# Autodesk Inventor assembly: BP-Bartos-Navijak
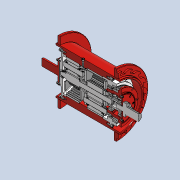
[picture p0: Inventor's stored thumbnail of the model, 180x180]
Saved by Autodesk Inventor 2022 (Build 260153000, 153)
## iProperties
Created: 2025-05
Part Number: BP-Bartos-Navijak
Document SubType Name: Assembly
Designer: jbart
Mass: 166693 g
Surface Area: 105788 cm^2
Volume: 131194 cm^3
Density: 1.27058 g/cm^3
Author: jbart
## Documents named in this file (39)
- C:\Users\jbart\OneDrive\Dokumenty\Inventor\Převodovka navijáku\BP-Bartos-Navijak.iam
- C:\Users\jbart\OneDrive\Dokumenty\Inventor\Převodovka navijáku\Bočnice.ipt
- C:\Users\jbart\OneDrive\Dokumenty\Inventor\Content Center Files\R2022\cs-CZ\CSN 02 4630\CSN 02 4630 - 6414.ipt
- C:\Users\jbart\OneDrive\Dokumenty\Inventor\Content Center Files\R2022\cs-CZ\CSN 02 2931\CSN 02 2931 - 180.ipt
- C:\Users\jbart\OneDrive\Dokumenty\Inventor\Převodovka navijáku\Víčko.ipt
- C:\Users\jbart\OneDrive\Dokumenty\Inventor\Převodovka navijáku\Pouzdro.ipt
- C:\Users\jbart\OneDrive\Dokumenty\Inventor\Content Center Files\R2022\cs-CZ\CSN 02 2930\CSN 02 2930 - 70.ipt
- C:\Users\jbart\OneDrive\Dokumenty\Inventor\Převodovka navijáku\Hřídel I.ipt
- C:\Users\jbart\OneDrive\Dokumenty\Inventor\Content Center Files\R2022\cs-CZ\CSN 02 2562  A\CSN 02 2562 - 16x10x50.ipt
- C:\Users\jbart\OneDrive\Dokumenty\Inventor\Content Center Files\R2022\cs-CZ\CSN 02 4720\CSN  02 4720 - 32952.ipt
- C:\Users\jbart\OneDrive\Dokumenty\Inventor\Content Center Files\R2022\cs-CZ\CSN 02 4720\CSN  02 4720 - 32948.ipt
- C:\Users\jbart\OneDrive\Dokumenty\Inventor\Převodovka navijáku\Pouzdro II.ipt
- C:\Users\jbart\OneDrive\Dokumenty\Inventor\Převodovka navijáku\Hřídel II.iam
- C:\Users\jbart\OneDrive\Dokumenty\Inventor\Content Center Files\R2022\cs-CZ\CSN 02 4630\CSN 02 4630 - 6208.ipt
- C:\Users\jbart\OneDrive\Dokumenty\Inventor\Content Center Files\R2022\cs-CZ\CSN 02 2930\CSN 02 2930 - 40.ipt
- C:\Users\jbart\OneDrive\Dokumenty\Inventor\Převodovka navijáku\Unášeč A-1.ipt
- C:\Users\jbart\OneDrive\Dokumenty\Inventor\Převodovka navijáku\Hřídel IV.ipt
- C:\Users\jbart\OneDrive\Dokumenty\Inventor\Převodovka navijáku\Distanční kroužek.ipt
- C:\Users\jbart\OneDrive\Dokumenty\Inventor\Content Center Files\R2022\cs-CZ\CSN 02 2930\CSN 02 2930 - 50.ipt
- C:\Users\jbart\OneDrive\Dokumenty\Inventor\Převodovka navijáku\Satelit A.iam
- C:\Users\jbart\OneDrive\Dokumenty\Inventor\Content Center Files\R2022\cs-CZ\CSN 02 4630\CSN 02 4630 - 6010.ipt
- C:\Users\jbart\OneDrive\Dokumenty\Inventor\Převodovka navijáku\Unášeč A-2.ipt
- C:\Users\jbart\OneDrive\Dokumenty\Inventor\Převodovka navijáku\Hřídel III.iam
- C:\Users\jbart\OneDrive\Dokumenty\Inventor\Převodovka navijáku\Distanční kroužek II.ipt
- C:\Users\jbart\OneDrive\Dokumenty\Inventor\Převodovka navijáku\Unášeč B-2.ipt
- C:\Users\jbart\OneDrive\Dokumenty\Inventor\Content Center Files\R2022\cs-CZ\CSN 02 1143  A\CSN 02 1143 - M12 x 1,75 x 20(1).ipt
- C:\Users\jbart\OneDrive\Dokumenty\Inventor\Content Center Files\R2022\cs-CZ\CSN 02 1143  A\CSN 02 1143 - M12 x 1,75 x 25(1).ipt
- C:\Users\jbart\OneDrive\Dokumenty\Inventor\Převodovka navijáku\Satelit B.iam
- C:\Users\jbart\OneDrive\Dokumenty\Inventor\Převodovka navijáku\Hřídel V.ipt
- C:\Users\jbart\OneDrive\Dokumenty\Inventor\Převodovka navijáku\Unášeč B-1.ipt
- C:\Users\jbart\OneDrive\Dokumenty\Inventor\Převodovka navijáku\Korunové kolo 2.iam
- C:\Users\jbart\OneDrive\Dokumenty\Inventor\Převodovka navijáku\Korunové kolo 1.iam
- C:\Users\jbart\OneDrive\Dokumenty\Inventor\Content Center Files\R2022\cs-CZ\CSN 02 1143  A\CSN 02 1143 - M16 x 2 x 45(1).ipt
- C:\Users\jbart\OneDrive\Dokumenty\Inventor\Převodovka navijáku\Víčko II.ipt
- C:\Users\jbart\OneDrive\Dokumenty\Inventor\Převodovka navijáku\Výstup.ipt
- C:\Users\jbart\OneDrive\Dokumenty\Inventor\Content Center Files\R2022\cs-CZ\CSN 02 1143  A\CSN 02 1143 - M12 x 1,75 x 22(1).ipt
- C:\Users\jbart\OneDrive\Dokumenty\Inventor\Převodovka navijáku\Buben - nový.iam
- C:\Users\jbart\OneDrive\Dokumenty\Inventor\Content Center Files\R2022\cs-CZ\CSN 02 9281\CSN 02 9281 - 16x2.ipt
- C:\Users\jbart\OneDrive\Dokumenty\Inventor\Content Center Files\R2022\cs-CZ\CSN 02 1143  A\CSN 02 1143 - M16 x 2 x 60(1).ipt
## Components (114 placed, 38 different names)
1. Bočnice:1 — Proti sobě:1, Stejný směr:1, Stejný směr:2, Proti sobě:2, Proti sobě:3, Proti sobě:4, Proti sobě:5, Proti sobě:6, Proti sobě:9, Proti sobě:10, Proti sobě:15, Proti sobě:16, Proti sobě:23, Proti sobě:24, Proti sobě:25, Proti sobě:26, Proti sobě:27, Proti sobě:37, Proti sobě:97, Proti sobě:98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
2. CSN 02 4630 6414:1 — Proti sobě:2, Proti sobě:3, Proti sobě:13, Proti sobě:14
3. CSN 02 2931 180:1 — Proti sobě:4, Proti sobě:5, Proti sobě:6
4. CSN 02 4630 6414:2
5. Víčko:1 — Proti sobě:9, Proti sobě:10, Proti sobě:16, Proti sobě:22, Proti sobě:99, Proti sobě:100
6. Pouzdro:1 — Proti sobě:11, Proti sobě:12, Proti sobě:13, Proti sobě:14, Proti sobě:20, Proti sobě:21, Proti sobě:30, Proti sobě:31, Proti sobě:32
7. CSN 02 2930 70:1 — Proti sobě:11, Proti sobě:12, Proti sobě:15
8. Hřídel I:1 — Proti sobě:20, Proti sobě:22, Proti sobě:176, Stejný směr:66
9. CSN 02 2562 A 16x10x50:1 — Proti sobě:21
10. CSN 02 4720 32952:1 — Proti sobě:23, Proti sobě:24, Proti sobě:28
11. CSN 02 4720 32948:1 — Proti sobě:25, Proti sobě:26
12. Pouzdro II:1 — Proti sobě:27, Proti sobě:28, Proti sobě:155, Proti sobě:157, Proti sobě:174, Proti sobě:175, Proti sobě:181
13. Hřídel II:1 [sub-assembly] — Proti sobě:30, Proti sobě:31, Proti sobě:32, Proti sobě:33, Proti sobě:34, Proti sobě:35, Proti sobě:36, Proti sobě:38, Stejný směr:59, Proti sobě:88, Proti sobě:91, Proti sobě:94, Proti sobě:96, Rotace:1, Rotace:2, Rotace:3, Rotace:4
14. CSN 02 4630 6208:1 — Proti sobě:33, Proti sobě:34
15. CSN 02 2930 40:1 — Proti sobě:35, Proti sobě:36, Proti sobě:37
16. Unášeč A-1:1 — Proti sobě:38, Proti sobě:53, Proti sobě:54, Proti sobě:55, Proti sobě:69, Proti sobě:70, Proti sobě:71, Proti sobě:85, Proti sobě:86, Proti sobě:87
17. Unášeč A-2:1 — Proti sobě:88, Proti sobě:90, Proti sobě:92, Proti sobě:93, Stejný směr:60, Rotace:4
18. Hřídel III:1 [sub-assembly] — Proti sobě:91, Proti sobě:93, Stejný směr:60, Proti sobě:95, Rotace:5, Rotace:6, Rotace:7, Rotace:8
19. Distanční kroužek II:1 — Proti sobě:94, Proti sobě:95
20. Unášeč B-2:1 — Proti sobě:96, Proti sobě:97, Proti sobě:98, Proti sobě:101, Proti sobě:102, Proti sobě:116, Proti sobě:117, Proti sobě:119, Proti sobě:133, Proti sobě:134, Proti sobě:135, Proti sobě:149, Proti sobě:150, Proti sobě:151, Proti sobě:152
21. Unášeč B-1:1 — Proti sobě:152, Proti sobě:153, Proti sobě:154
22. Korunové kolo 2:1 [sub-assembly] — Proti sobě:155, Stejný směr:62, Stejný směr:64, Rotace:8, Proti sobě:177
23. Korunové kolo 1:1 [sub-assembly] — Proti sobě:157, Stejný směr:63, Proti sobě:178
24. Víčko II:1 — Proti sobě:166, Proti sobě:167, Proti sobě:168, Proti sobě:169, Proti sobě:170
25. Výstup:1 — Proti sobě:168, Proti sobě:169, Proti sobě:170, Proti sobě:171, Proti sobě:172
26. Buben - nový:1 [sub-assembly] — Proti sobě:176, Proti sobě:177, Proti sobě:178, Proti sobě:179, Proti sobě:180, Proti sobě:181, Proti sobě:182, Proti sobě:183, Proti sobě:184, Proti sobě:185
27. CSN 02 1143 A M16 x 60:1 — Proti sobě:184, Proti sobě:185
28. CSN 02 9281 16x2:1 — Proti sobě:182, Proti sobě:183
29. Hřídel IV:1 — Proti sobě:53, Proti sobě:92
30. Distanční kroužek:1 — Proti sobě:55
31. Distanční kroužek:2 — Proti sobě:90
32. CSN 02 2930 50:1
33. CSN 02 2930 50:2 — Proti sobě:54
34. Satelit A:1 [sub-assembly] — Stejný směr:59, Stejný směr:63, Rotace:1
35. CSN 02 4630 6010:1
36. CSN 02 4630 6010:2
37. Hřídel IV:2 — Proti sobě:69
38. Distanční kroužek:3
39. Distanční kroužek:4
40. CSN 02 2930 50:3
41. CSN 02 2930 50:4 — Proti sobě:70
42. Satelit A:2 [sub-assembly] — Rotace:2
43. CSN 02 4630 6010:3 — Proti sobě:71
44. CSN 02 4630 6010:4
45. Hřídel IV:3 — Proti sobě:85
46. Distanční kroužek:5 — Proti sobě:87
47. Distanční kroužek:6
48. CSN 02 2930 50:5
49. CSN 02 2930 50:6 — Proti sobě:86
50. Satelit A:3 [sub-assembly] — Rotace:3
51. CSN 02 4630 6010:5
52. CSN 02 4630 6010:6
53. Satelit B:1 [sub-assembly] — Rotace:5
54. Hřídel V:1 — Proti sobě:116, Proti sobě:153
55. CSN 02 4630 6010:7
56. CSN 02 4630 6010:8
57. Distanční kroužek:7
58. Distanční kroužek:8 — Proti sobě:119
59. CSN 02 2930 50:7
60. CSN 02 2930 50:8 — Proti sobě:117, Proti sobě:118
61. Satelit B:2 [sub-assembly] — Stejný směr:62, Rotace:7
62. Hřídel V:2 — Proti sobě:133
63. CSN 02 4630 6010:9
64. CSN 02 4630 6010:10
65. Distanční kroužek:9 — Proti sobě:154
66. Distanční kroužek:10 — Proti sobě:135
67. CSN 02 2930 50:9
68. CSN 02 2930 50:10 — Proti sobě:134
69. Satelit B:3 [sub-assembly] — Rotace:6
70. Hřídel V:3 — Proti sobě:149
71. CSN 02 4630 6010:11
72. CSN 02 4630 6010:12
73. Distanční kroužek:11
74. Distanční kroužek:12 — Proti sobě:151
75. CSN 02 2930 50:11
76. CSN 02 2930 50:12 — Proti sobě:150
77. CSN 02 1143 A M12 x 20:1 — Proti sobě:99, Proti sobě:100
78. CSN 02 1143 A M12 x 20:2
79. CSN 02 1143 A M12 x 20:3
80. CSN 02 1143 A M12 x 20:4
81. CSN 02 1143 A M12 x 20:5
82. CSN 02 1143 A M12 x 20:6
83. CSN 02 1143 A M12 x 20:7
84. CSN 02 1143 A M12 x 20:8
85. CSN 02 1143 A M12 x 25:1 — Proti sobě:101, Proti sobě:102
86. CSN 02 1143 A M12 x 25:2
87. CSN 02 1143 A M12 x 25:3
88. CSN 02 1143 A M12 x 25:4
89. CSN 02 1143 A M12 x 25:5
90. CSN 02 1143 A M12 x 25:6
91. CSN 02 1143 A M16 x 45:9 — Proti sobě:166, Proti sobě:167
92. CSN 02 1143 A M16 x 45:10 — Proti sobě:180
93. CSN 02 1143 A M16 x 45:11
94. CSN 02 1143 A M16 x 45:12
95. CSN 02 1143 A M16 x 45:13
96. CSN 02 1143 A M16 x 45:14
97. CSN 02 1143 A M16 x 45:15
98. CSN 02 1143 A M16 x 45:16
99. CSN 02 1143 A M12 x 22:1 — Proti sobě:171, Proti sobě:172
100. CSN 02 1143 A M12 x 22:2
101. CSN 02 1143 A M12 x 22:3
102. CSN 02 1143 A M12 x 22:4
103. CSN 02 1143 A M12 x 22:5
104. CSN 02 1143 A M12 x 22:6
105. CSN 02 1143 A M12 x 22:7
106. CSN 02 1143 A M12 x 22:8
107. CSN 02 1143 A M16 x 45:1 — Proti sobě:174, Proti sobě:175, Proti sobě:179
108. CSN 02 1143 A M16 x 45:17
109. CSN 02 1143 A M16 x 45:18
110. CSN 02 1143 A M16 x 45:19
111. CSN 02 1143 A M16 x 45:20
112. CSN 02 1143 A M16 x 45:21
113. CSN 02 1143 A M16 x 45:22
114. CSN 02 1143 A M16 x 45:23
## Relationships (106: Mate 89, Flush 9, RelateRotation 8)
- Proti sobě:1 [Mate]: Bočnice:1
- Stejný směr:1 [Flush]: Bočnice:1
- Stejný směr:2 [Flush]: Bočnice:1
- Proti sobě:2 [Mate]: Bočnice:1 ↔ CSN 02 4630 6414:1
- Proti sobě:3 [Mate]: Bočnice:1 ↔ CSN 02 4630 6414:1
- Proti sobě:4 [Mate]: Bočnice:1 ↔ CSN 02 2931 180:1
- Proti sobě:5 [Mate]: Bočnice:1 ↔ CSN 02 2931 180:1
- Proti sobě:6 [Mate]: Bočnice:1 ↔ CSN 02 2931 180:1
- Proti sobě:9 [Mate]: Bočnice:1 ↔ Víčko:1
- Proti sobě:10 [Mate]: Bočnice:1 ↔ Víčko:1
- Proti sobě:11 [Mate]: Pouzdro:1 ↔ CSN 02 2930 70:1
- Proti sobě:12 [Mate]: Pouzdro:1 ↔ CSN 02 2930 70:1
- Proti sobě:13 [Mate]: CSN 02 4630 6414:1 ↔ Pouzdro:1
- Proti sobě:14 [Mate]: CSN 02 4630 6414:1 ↔ Pouzdro:1
- Proti sobě:15 [Mate]: Bočnice:1 ↔ CSN 02 2930 70:1
- Proti sobě:16 [Mate]: Bočnice:1 ↔ Víčko:1
- Proti sobě:20 [Mate]: Pouzdro:1 ↔ Hřídel I:1
- Proti sobě:21 [Mate]: Pouzdro:1 ↔ CSN 02 2562 A 16x10x50:1
- Proti sobě:22 [Mate]: Víčko:1 ↔ Hřídel I:1
- Proti sobě:23 [Mate]: Bočnice:1 ↔ CSN 02 4720 32952:1
- Proti sobě:24 [Mate]: Bočnice:1 ↔ CSN 02 4720 32952:1
- Proti sobě:25 [Mate]: Bočnice:1 ↔ CSN 02 4720 32948:1
- Proti sobě:26 [Mate]: Bočnice:1 ↔ CSN 02 4720 32948:1
- Proti sobě:27 [Mate]: Bočnice:1 ↔ Pouzdro II:1
- Proti sobě:28 [Mate]: CSN 02 4720 32952:1 ↔ Pouzdro II:1
- Proti sobě:30 [Mate]: Pouzdro:1 ↔ Hřídel II:1
- Proti sobě:31 [Mate]: Pouzdro:1 ↔ Hřídel II:1
- Proti sobě:32 [Mate]: Pouzdro:1 ↔ Hřídel II:1
- Proti sobě:33 [Mate]: Hřídel II:1 ↔ CSN 02 4630 6208:1
- Proti sobě:34 [Mate]: Hřídel II:1 ↔ CSN 02 4630 6208:1
- Proti sobě:35 [Mate]: Hřídel II:1 ↔ CSN 02 2930 40:1
- Proti sobě:36 [Mate]: Hřídel II:1 ↔ CSN 02 2930 40:1
- Proti sobě:37 [Mate]: Bočnice:1 ↔ CSN 02 2930 40:1
- Proti sobě:38 [Mate]: Hřídel II:1 ↔ Unášeč A-1:1
- Proti sobě:53 [Mate]: Unášeč A-1:1 ↔ Hřídel IV:1
- Proti sobě:54 [Mate]: Unášeč A-1:1 ↔ CSN 02 2930 50:2
- Proti sobě:55 [Mate]: Unášeč A-1:1 ↔ Distanční kroužek:1
- Proti sobě:69 [Mate]: Unášeč A-1:1 ↔ Hřídel IV:2
- Proti sobě:70 [Mate]: Unášeč A-1:1 ↔ CSN 02 2930 50:4
- Proti sobě:71 [Mate]: Unášeč A-1:1 ↔ CSN 02 4630 6010:3
- Proti sobě:85 [Mate]: Unášeč A-1:1 ↔ Hřídel IV:3
- Proti sobě:86 [Mate]: Unášeč A-1:1 ↔ CSN 02 2930 50:6
- Proti sobě:87 [Mate]: Unášeč A-1:1 ↔ Distanční kroužek:5
- Stejný směr:59 [Flush]: Hřídel II:1 ↔ Satelit A:1
- Proti sobě:88 [Mate]: Hřídel II:1 ↔ Unášeč A-2:1
- Proti sobě:90 [Mate]: Unášeč A-2:1 ↔ Distanční kroužek:2
- Proti sobě:91 [Mate]: Hřídel II:1 ↔ Hřídel III:1
- Proti sobě:92 [Mate]: Unášeč A-2:1 ↔ Hřídel IV:1
- Proti sobě:93 [Mate]: Unášeč A-2:1 ↔ Hřídel III:1
- Stejný směr:60 [Flush]: Unášeč A-2:1 ↔ Hřídel III:1
- Proti sobě:94 [Mate]: Hřídel II:1 ↔ Distanční kroužek II:1
- Proti sobě:95 [Mate]: Hřídel III:1 ↔ Distanční kroužek II:1
- Proti sobě:96 [Mate]: Hřídel II:1 ↔ Unášeč B-2:1
- Proti sobě:97 [Mate]: Bočnice:1 ↔ Unášeč B-2:1
- Proti sobě:98 [Mate]: Bočnice:1 ↔ Unášeč B-2:1
- Proti sobě:99 [Mate]: Víčko:1 ↔ CSN 02 1143 A M12 x 20:1
- Proti sobě:100 [Mate]: Víčko:1 ↔ CSN 02 1143 A M12 x 20:1
- Proti sobě:101 [Mate]: Unášeč B-2:1 ↔ CSN 02 1143 A M12 x 25:1
- Proti sobě:102 [Mate]: Unášeč B-2:1 ↔ CSN 02 1143 A M12 x 25:1
- Proti sobě:116 [Mate]: Unášeč B-2:1 ↔ Hřídel V:1
- Proti sobě:117 [Mate]: Unášeč B-2:1 ↔ CSN 02 2930 50:8
- Proti sobě:118 [Mate]: Bočnice:1 ↔ CSN 02 2930 50:8
- Proti sobě:119 [Mate]: Unášeč B-2:1 ↔ Distanční kroužek:8
- Proti sobě:133 [Mate]: Unášeč B-2:1 ↔ Hřídel V:2
- Proti sobě:134 [Mate]: Unášeč B-2:1 ↔ CSN 02 2930 50:10
- Proti sobě:135 [Mate]: Unášeč B-2:1 ↔ Distanční kroužek:10
- Proti sobě:149 [Mate]: Unášeč B-2:1 ↔ Hřídel V:3
- Proti sobě:150 [Mate]: Unášeč B-2:1 ↔ CSN 02 2930 50:12
- Proti sobě:151 [Mate]: Unášeč B-2:1 ↔ Distanční kroužek:12
- Proti sobě:152 [Mate]: Unášeč B-2:1 ↔ Unášeč B-1:1
- Proti sobě:153 [Mate]: Unášeč B-1:1 ↔ Hřídel V:1
- Proti sobě:154 [Mate]: Unášeč B-1:1 ↔ Distanční kroužek:9
- Proti sobě:155 [Mate]: Pouzdro II:1 ↔ Korunové kolo 2:1
- Stejný směr:62 [Flush]: Korunové kolo 2:1 ↔ Satelit B:2
- Proti sobě:157 [Mate]: Pouzdro II:1 ↔ Korunové kolo 1:1
- Stejný směr:63 [Flush]: Korunové kolo 1:1 ↔ Satelit A:1
- Stejný směr:64 [Flush]: Korunové kolo 2:1
- Proti sobě:166 [Mate]: Víčko II:1 ↔ CSN 02 1143 A M16 x 45:9
- Proti sobě:167 [Mate]: Víčko II:1 ↔ CSN 02 1143 A M16 x 45:9
- Proti sobě:168 [Mate]: Víčko II:1 ↔ Výstup:1
- Proti sobě:169 [Mate]: Víčko II:1 ↔ Výstup:1
- Proti sobě:170 [Mate]: Víčko II:1 ↔ Výstup:1
- Proti sobě:171 [Mate]: Výstup:1 ↔ CSN 02 1143 A M12 x 22:1
- Proti sobě:172 [Mate]: Výstup:1 ↔ CSN 02 1143 A M12 x 22:1
- Stejný směr:65 [Flush]: Bočnice:1
- Rotace:1 [RelateRotation]: Hřídel II:1 ↔ Satelit A:1
- Rotace:2 [RelateRotation]: Hřídel II:1 ↔ Satelit A:2
- Rotace:3 [RelateRotation]: Hřídel II:1 ↔ Satelit A:3
- Rotace:4 [RelateRotation]: Hřídel II:1 ↔ Unášeč A-2:1
- Rotace:5 [RelateRotation]: Hřídel III:1 ↔ Satelit B:1
- Rotace:6 [RelateRotation]: Hřídel III:1 ↔ Satelit B:3
- Rotace:7 [RelateRotation]: Hřídel III:1 ↔ Satelit B:2
- Rotace:8 [RelateRotation]: Hřídel III:1 ↔ Korunové kolo 2:1
- Proti sobě:174 [Mate]: Pouzdro II:1 ↔ CSN 02 1143 A M16 x 45:1
- Proti sobě:175 [Mate]: Pouzdro II:1 ↔ CSN 02 1143 A M16 x 45:1
- Proti sobě:176 [Mate]: Hřídel I:1 ↔ Buben - nový:1
- Proti sobě:177 [Mate]: Korunové kolo 2:1 ↔ Buben - nový:1
- Proti sobě:178 [Mate]: Korunové kolo 1:1 ↔ Buben - nový:1
- Proti sobě:179 [Mate]: Buben - nový:1 ↔ CSN 02 1143 A M16 x 45:1
- Proti sobě:180 [Mate]: Buben - nový:1 ↔ CSN 02 1143 A M16 x 45:10
- Proti sobě:181 [Mate]: Pouzdro II:1 ↔ Buben - nový:1
- Proti sobě:182 [Mate]: Buben - nový:1 ↔ CSN 02 9281 16x2:1
- Proti sobě:183 [Mate]: Buben - nový:1 ↔ CSN 02 9281 16x2:1
- Proti sobě:184 [Mate]: Buben - nový:1 ↔ CSN 02 1143 A M16 x 60:1
- Proti sobě:185 [Mate]: Buben - nový:1 ↔ CSN 02 1143 A M16 x 60:1
- Stejný směr:66 [Flush]: Hřídel I:1
## Named parameters: d19_d13 = 0, d20_d14 = 0, d21_d15 = 0, d61_d108 = 0, d62_d109 = 0, d63_d110 = 0, d64_d111 = 0, d65_d112 = 0, d66_d113 = 0, d67_d114 = 0, d68_d115 = 0, d69_d116 = 0, d70_d117 = 0, d71_d118 = 0, d72_d119 = 0, d73_d107 = 0, d77_d108 = 0, d78_d109 = 0, d79_d110 = 0, d80_d111 = 0, d81_d112 = 0, d82_d113 = 0, d83_d114 = 0, d84_d115 = 0, d85_d116 = 0, d86_d117 = 0, d87_d118 = 0, d88_d119 = 0, d89_d107 = 0, d66_d56 = 0, d67_d57 = 0, d68_d58 = 0, d69_d46 = 0, d70_d47 = 0, d71_d48 = 0, d72_d49 = 0, d73_d50 = 0, d74_d51 = 0, d75_d52 = 0, d76_d53 = 0, d77_d54 = 0, d78_d55 = 0, d145_d66_d56 = 0, d146_d67_d57 = 0, d147_d68_d58 = 0, d148_d69_d46 = 0, d149_d70_d47 = 0, d150_d71_d48 = 0, d151_d72_d49 = 0, d152_d73_d50 = 0, d153_d74_d51 = 0, d154_d75_d52 = 0, d155_d76_d53 = 0, d156_d77_d54 = 0, d157_d78_d55 = 0, d161_d66_d56 = 0, d162_d67_d57 = 0, d163_d68_d58 = 0, d164_d69_d46 = 0, d165_d70_d47 = 0, d166_d71_d48 = 0, d167_d72_d49 = 0, d168_d73_d50 = 0, d169_d74_d51 = 0, d170_d75_d52 = 0, d171_d76_d53 = 0, d174_d77_d54 = 0, d175_d78_d55 = 0
